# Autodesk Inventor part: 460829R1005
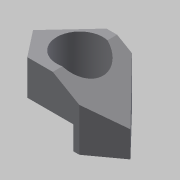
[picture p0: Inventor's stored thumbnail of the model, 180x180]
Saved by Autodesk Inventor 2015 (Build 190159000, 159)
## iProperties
Created: 2016-08
Part Number: 460829R1005
Material: 일반
Document SubType Name: Modeling
Designer: jio
Density: 1 g/cm^3
Appearance: 기본값
Author: jio
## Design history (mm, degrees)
sketch "스케치1"
  geometry: L1 (-9.387, 55)-(34, 55); L2 (34, 55)-(104.673, -18.184); L3 (-34.842, -55)-(-70, -10); L4 (-70, -10)-(-9.387, 55); L5 (-34.842, -55)-(54, -55); L6 (104.673, -18.184)-(54, -55); C1 r 39.5 at (0, 0); 1 further point
  constraints: 12 end point, 2 horizontal, 1 centre point, 1 coincident
  dimensions: "d0" = 79 diameter of C1; "d1" = 134 deg angle of L2 L1; "d5" = 99 deg angle of L3 L4; "d7" = 110 vertical distance of L3.start L1.start; "d8" = 45 vertical distance of L3.start L3.end; "d11" = 144 deg angle of L6 L5; "d12" = 124 horizontal distance of L3.end L5.end; "d13" = 104 horizontal distance of L1.end L3.end; "d14" = 70 horizontal distance of point (0, 0) L3.end; "d15" = 55 distance from line of L5 point (0, 0); "d16" = 128 deg angle of L3 L5
extrude "돌출1" new body sketch "스케치1" distance "d17" = 100; taper "d18" = 0 deg
sketch "스케치2"
  geometry: L1 (0, 100)-(88.842, 100) reference; L2 (43.515, 100)-(139.515, 100); L3 (139.515, 100)-(139.515, 44.574); L4 (139.515, 44.574)-(43.515, 100); L5 (139.515, 0)-(139.515, 100) reference; L6 (88.842, 100)-(139.515, 100) reference; 1 further point
  constraints: 6 end point, 2 collinear, 1 horizontal, 1 perpendicular
  dimensions: "d19" = 96 distance of L2.start L2.end; "d20" = 30 deg angle of L4 L1
extrude "돌출2" cut sketch "스케치2" stored distance "d21" = 100; taper "d22" = 0 deg
sketch "스케치3"
  geometry: L1 (-35.158, 40)-(78.842, 40); L2 (78.842, 40)-(78.842, 0); L3 (78.842, 0)-(-35.158, 0); L4 (-35.158, 0)-(-35.158, 40); 2 further points
  constraints: 8 end point, 2 parallel, 1 coincident, 1 horizontal, 1 perpendicular
  dimensions: "d23" = 40 distance between parallel lines of L3 L1; "d24" = 114 distance of L2.end L3.end
extrude "돌출3" cut sketch "스케치3" distance "d25" = 70; taper "d26" = 0 deg
node "솔리드1"
